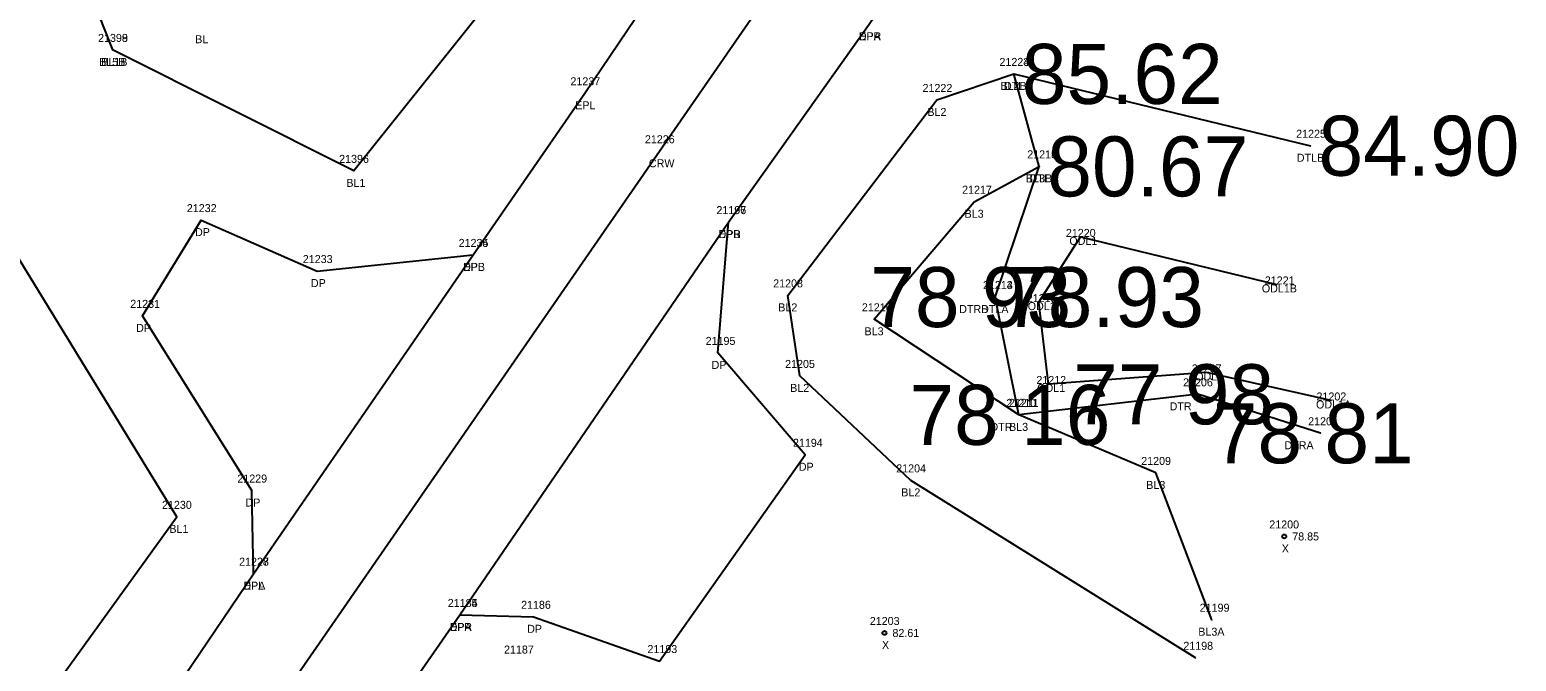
# Model space of a CAD drawing. Extents: x 2266664 to 2272385, y 716533 to 724777.
# Drawn here: x 2269825.5 to 2270011.2, y 721129.7 to 721208.7 of the extents above; entities that cross this region are included whole.
import ezdxf

# ---------------------------------------------------------------- set-up
doc = ezdxf.new("R2010")
doc.units = 0
for name, color, linetype in [('RD_DTM_BkLn1', 7, 'Continuous'), ('RD_EX_DR_Inlet_txCode', 7, 'Continuous'), ('RD_EX_Driveway', 7, 'Continuous'), ('RD_EX_Driveway_txCode', 7, 'Continuous'), ('RD_EX_H2O', 7, 'Continuous'), ('RD_EX_H2O_txCode', 7, 'Continuous'), ('RD_EX_Road', 7, 'Continuous'), ('RD_EX_Road_txCode', 7, 'Continuous'), ('RD_Sketch8', 7, 'Continuous'), ('RD_SMD_Locator', 7, 'Continuous'), ('RD_SMD_Misc', 7, 'Continuous')]:
    doc.layers.add(name, color=color, linetype=linetype)

msp = doc.modelspace()

# ---------------------------------------------------------------- linework, layer by layer
at = {"layer": 'RD_DTM_BkLn1'}
for points in [[(2269874.61, 721338.02), (2269859.38, 721330.7), (2269818.8, 721249.22), (2269835.85, 721206.17)], [(2269959.65, 721302.4), (2269953.17, 721302.14), (2269938.41, 721285.97), (2269897.06, 721229.9), (2269866, 721191.05), (2269835.85, 721206.17)], [(2269213.98, 720188.15), (2269268.31, 720269.94), (2269268.47, 720270.09), (2269327.62, 720355.72), (2269383.6, 720437.51), (2269437.73, 720515.95), (2269495.99, 720600.52), (2269554.62, 720685.64), (2269615.22, 720774.38), (2269673.5, 720859.19), (2269731.5, 720942.79), (2269790.07, 721028.11), (2269844, 721106.36), (2269904.2, 721193.5), (2269962.45, 721277.81), (2269974.66, 721295.97), (2269974.85, 721296.23)], [(2269971.16, 721130.17), (2269935.62, 721152.35), (2269921.74, 721165.41), (2269920.25, 721175.48), (2269938.87, 721199.91), (2269948.48, 721203.17)], [(2269973.21, 721134.93), (2269966.23, 721153.28), (2269949.09, 721160.54), (2269931.03, 721172.49), (2269943.52, 721187.19), (2269951.66, 721191.61)], [(2269191.51, 720201.26), (2269187.85, 720205.58), (2269199.52, 720217.6), (2269246.59, 720287.4), (2269307.32, 720370.14), (2269357.23, 720449.48), (2269408.57, 720538.5), (2269423.88, 720580.07), (2269441.65, 720584.31), (2269472.47, 720620.26), (2269529.45, 720703.37), (2269589.67, 720791.77), (2269652.08, 720873.67), (2269703.1, 720960.72), (2269760.35, 721047.31), (2269823.22, 721119.06), (2269843.89, 721147.79), (2269820.55, 721185.92)]]:
    msp.add_lwpolyline(points, dxfattribs=at)
at = {"layer": 'RD_EX_Driveway'}
for points in [[(2269853.48, 721140.68), (2269853.26, 721151.08), (2269839.59, 721172.92), (2269846.95, 721184.89), (2269861.43, 721178.52), (2269880.91, 721180.54)], [(2269879.26, 721135.52), (2269888.45, 721135.29), (2269904.22, 721129.76), (2269922.39, 721155.55), (2269911.49, 721168.29), (2269912.84, 721184.64)]]:
    msp.add_lwpolyline(points, dxfattribs=at)
at = {"layer": 'RD_EX_H2O'}
for points in [[(2269946.13, 721175.27), (2269951.66, 721191.61), (2269948.48, 721203.17), (2269985.54, 721194.19)], [(2269988.13, 721162.34), (2269972.54, 721165.85), (2269952.8, 721164.4), (2269951.61, 721174.64), (2269956.82, 721182.79), (2269981.35, 721176.85)], [(2269986.8, 721158.24), (2269971.48, 721163.11), (2269949.09, 721160.54), (2269946.13, 721175.27)]]:
    msp.add_lwpolyline(points, dxfattribs=at)
at = {"layer": 'RD_EX_Road'}
for points in [[(2269202.93, 720196.07), (2269237.22, 720244.72), (2269259.4, 720276.99), (2269259.41, 720277.21), (2269317.32, 720361.94), (2269369.05, 720437.36), (2269428.45, 720522.87), (2269487.41, 720608.15), (2269502.81, 720630.76), (2269544.96, 720692.14), (2269605.63, 720780.46), (2269663.95, 720865.82), (2269721.16, 720948.73), (2269780.45, 721034.57), (2269834.47, 721112.56), (2269853.48, 721140.68), (2269880.91, 721180.54), (2269894.87, 721200.75), (2269951.76, 721285.08), (2269965.67, 721302.04), (2269963.39, 721303.74)], [(2269222.47, 720182.37), (2269278.1, 720262.57), (2269277.83, 720263.03), (2269337.43, 720348.71), (2269393.72, 720430.44), (2269448.55, 720510.19), (2269506.62, 720593.92), (2269564.83, 720678.53), (2269625.78, 720767.57), (2269683.68, 720852.02), (2269741.8, 720936.18), (2269800.12, 721020.89), (2269854.32, 721099.54), (2269879.26, 721135.52), (2269912.84, 721184.64), (2269930.38, 721209.38), (2269961.18, 721254.67), (2269975.2, 721274.82), (2269984.48, 721289.11), (2269986.54, 721288.04)]]:
    msp.add_lwpolyline(points, dxfattribs=at)
at = {"layer": 'RD_SMD_Locator'}
for centre, radius in [((2269835.85, 721206.17), 0.001), ((2269835.85, 721206.17), 0.001), ((2269948.48, 721203.17), 0.001), ((2269948.48, 721203.17), 0.001), ((2269894.87, 721200.75), 0.001), ((2269938.87, 721199.91), 0.001), ((2269904.2, 721193.5), 0.001), ((2269985.54, 721194.19), 0.001), ((2269866, 721191.05), 0.001), ((2269951.66, 721191.61), 0.001), ((2269951.66, 721191.61), 0.001), ((2269943.52, 721187.19), 0.001), ((2269846.95, 721184.89), 0.001), ((2269912.84, 721184.64), 0.001), ((2269912.84, 721184.64), 0.001), ((2269956.82, 721182.79), 0.001), ((2269880.91, 721180.54), 0.001), ((2269880.91, 721180.54), 0.001), ((2269861.43, 721178.52), 0.001), ((2269981.35, 721176.85), 0.001), ((2269920.25, 721175.48), 0.001), ((2269946.13, 721175.27), 0.001), ((2269946.13, 721175.27), 0.001), ((2269951.61, 721174.64), 0.001), ((2269839.59, 721172.92), 0.001), ((2269931.03, 721172.49), 0.001), ((2269911.49, 721168.29), 0.001), ((2269921.74, 721165.41), 0.001), ((2269972.54, 721165.85), 0.001), ((2269952.8, 721164.4), 0.001), ((2269971.48, 721163.11), 0.001), ((2269988.13, 721162.34), 0.001), ((2269949.09, 721160.54), 0.001), ((2269949.09, 721160.54), 0.001), ((2269986.8, 721158.24), 0.001), ((2269922.39, 721155.55), 0.001), ((2269935.62, 721152.35), 0.001), ((2269966.23, 721153.28), 0.001), ((2269853.26, 721151.08), 0.001), ((2269843.89, 721147.79), 0.001), ((2269982.26, 721145.34), 0.25), ((2269853.48, 721140.68), 0.001), ((2269853.48, 721140.68), 0.001), ((2269879.26, 721135.52), 0.001), ((2269879.26, 721135.52), 0.001), ((2269888.45, 721135.29), 0.001), ((2269932.31, 721133.27), 0.25), ((2269973.21, 721134.93), 0.001), ((2269904.22, 721129.76), 0.001), ((2269971.16, 721130.17), 0.001)]:
    msp.add_circle(centre, radius, dxfattribs=at)

# ---------------------------------------------------------------- texts
at = {"layer": 'RD_EX_DR_Inlet_txCode'}
for s, p in [('85.62', (2269949.48, 721199.42)), ('84.90', (2269986.54, 721190.44)), ('80.67', (2269952.66, 721187.86)), ('78 93', (2269930.54, 721171.52)), ('78.93', (2269947.13, 721171.52)), ('77 98', (2269955.89, 721159.36)), ('78 16', (2269935.44, 721156.79)), ('78 81', (2269973.34, 721154.49))]:
    msp.add_text(s, height=7.5, dxfattribs=at).set_placement(p)
at = {"layer": 'RD_EX_Driveway_txCode'}
for s, p in [('DPA', (2269929.11, 721207.38)), ('21232', (2269845.15, 721185.89)), ('21196', (2269911.31, 721185.64)), ('DP', (2269846.17, 721182.89)), ('DPB', (2269911.59, 721182.64)), ('21234', (2269879.11, 721181.54)), ('21233', (2269859.64, 721179.52)), ('DPB', (2269879.66, 721178.54)), ('DP', (2269860.65, 721176.52)), ('21231', (2269838.08, 721173.92)), ('DP', (2269838.81, 721170.92)), ('21195', (2269909.97, 721169.29)), ('DP', (2269910.71, 721166.29)), ('21194', (2269920.88, 721156.55)), ('DP', (2269921.61, 721153.55)), ('21229', (2269851.46, 721152.08)), ('DP', (2269852.48, 721149.08)), ('21228', (2269851.68, 721141.68)), ('DPA', (2269852.21, 721138.68)), ('21185', (2269877.75, 721136.52)), ('21186', (2269886.91, 721136.29)), ('DPA', (2269877.99, 721133.52)), ('DP', (2269887.67, 721133.29)), ('21193', (2269902.7, 721130.76))]:
    msp.add_text(s, height=1, dxfattribs=at).set_placement(p)
at = {"layer": 'RD_EX_H2O_txCode'}
for s, p in [('21224', (2269946.68, 721204.17)), ('DTL', (2269947.24, 721201.17)), ('21225', (2269983.75, 721195.19)), ('21219', (2269950.15, 721192.61)), ('DTLB', (2269983.83, 721192.19)), ('DTL', (2269950.42, 721189.61)), ('21220', (2269954.98, 721182.79)), ('ODL1', (2269955.41, 721181.79)), ('21213', (2269944.62, 721176.27)), ('21214', (2269944.62, 721176.27)), ('ODL1B', (2269979.46, 721175.85)), ('21221', (2269979.83, 721176.85)), ('DTRB', (2269941.65, 721173.27)), ('DTLA', (2269944.39, 721173.27)), ('21215', (2269950.1, 721174.64)), ('ODL1', (2269950.21, 721173.64)), ('21207', (2269970.71, 721165.85)), ('21212', (2269951.29, 721164.4)), ('21206', (2269969.62, 721164.11)), ('ODL1', (2269971.13, 721164.85)), ('ODL1', (2269951.39, 721163.4)), ('21202', (2269986.29, 721162.34)), ('21210', (2269947.54, 721161.54)), ('DTR', (2269967.94, 721161.11)), ('ODL1A', (2269986.23, 721161.34)), ('DTR', (2269945.55, 721158.54)), ('21201', (2269985.25, 721159.24)), ('DTRA', (2269982.29, 721156.24))]:
    msp.add_text(s, height=1, dxfattribs=at).set_placement(p)
at = {"layer": 'RD_EX_Road_txCode'}
for s, p in [('EPR', (2269929.15, 721207.38)), ('21237', (2269893.08, 721201.75)), ('EPL', (2269893.67, 721198.75)), ('21197', (2269911.33, 721185.64)), ('EPR', (2269911.61, 721182.64)), ('21235', (2269879.11, 721181.54)), ('EPL', (2269879.7, 721178.54)), ('21227', (2269851.68, 721141.68)), ('EPL', (2269852.27, 721138.68)), ('21184', (2269877.75, 721136.52)), ('EPR', (2269878.03, 721133.52))]:
    msp.add_text(s, height=1, dxfattribs=at).set_placement(p)
at = {"layer": 'RD_Sketch8'}
for s, p in [('21200', (2269980.39, 721146.34)), ('78.85', (2269983.26, 721144.84)), ('X', (2269981.95, 721143.34)), ('21203', (2269930.48, 721134.27)), ('82.61', (2269933.31, 721132.77)), ('X', (2269932, 721131.27))]:
    msp.add_text(s, height=1, dxfattribs=at).set_placement(p)
at = {"layer": 'RD_SMD_Misc'}
for s, p in [('21398', (2269834.06, 721207.17)), ('21399', (2269834.06, 721207.17)), ('BL', (2269846.19, 721207.01)), ('BL5B', (2269834.18, 721204.17)), ('BL1B', (2269834.46, 721204.17)), ('21223', (2269946.68, 721204.17)), ('BL2B', (2269946.8, 721201.17)), ('21222', (2269937.07, 721200.91)), ('BL2', (2269937.67, 721197.91)), ('21226', (2269902.38, 721194.5)), ('21396', (2269864.18, 721192.05)), ('21218', (2269950.15, 721192.61)), ('CRW', (2269902.88, 721191.5)), ('BL1', (2269865.08, 721189.05)), ('21217', (2269942.01, 721188.19)), ('BL3B', (2269949.98, 721189.61)), ('BL3', (2269942.32, 721185.19)), ('21208', (2269918.41, 721176.48)), ('BL2', (2269919.04, 721173.48)), ('21216', (2269929.49, 721173.49)), ('BL3', (2269929.82, 721170.49)), ('21205', (2269919.9, 721166.41)), ('BL2', (2269920.53, 721163.41)), ('21211', (2269947.86, 721161.54)), ('BL3', (2269947.88, 721158.54)), ('21204', (2269933.78, 721153.35)), ('21209', (2269964.39, 721154.28)), ('BL3', (2269965.02, 721151.28)), ('BL2', (2269934.41, 721150.35)), ('21230', (2269842.05, 721148.79)), ('BL1', (2269842.97, 721145.79)), ('21199', (2269971.7, 721135.93)), ('BL3A', (2269971.52, 721132.93)), ('21187', (2269884.78, 721130.7)), ('21198', (2269969.65, 721131.17))]:
    msp.add_text(s, height=1, dxfattribs=at).set_placement(p)

doc.saveas('drawing.dxf')
